(* Logix 5000 project; controller MVI56ADMNETServer 1756-L63 rev 11.1; software revision 11.13 *)
// Example Logic for the MVI56-ADM module.

TASK MainTask (task) : MainProgram

MODULES
   Local : 1756-L63 (rev 11.1)
      ADM : vendor 1 type 0 code 15 (rev 1.1, Output RPI 2 ms)
END_MODULES

TYPE ADMNETModuleDef :
STRUCT
   ReadData : INT[600];
   WriteData : INT[600];
END_STRUCT
END_TYPE

VAR_GLOBAL   (* controller tags *)
   ADMNET : ADMNETModuleDef;
   ColdBoot : BOOL;
   MJFAULTS : DINT[12] := ([0] := -491726278, [1] := 191080, [3] := -495837906, [4] := 191080);
   WarmBoot : BOOL;
END_VAR

PROGRAM MainProgram   (* routine attr 65 MainRoutine *)

ROUTINE MainRoutine   (* ladder *)
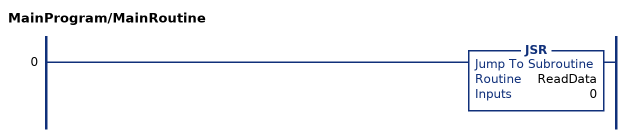
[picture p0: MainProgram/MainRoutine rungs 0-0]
   0: JSR(ReadData,0);
END_ROUTINE

ROUTINE ReadData   (* ladder *)
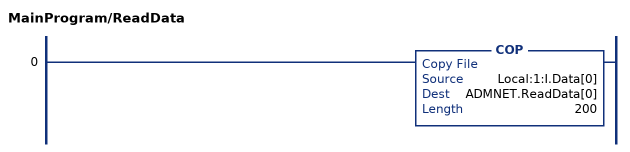
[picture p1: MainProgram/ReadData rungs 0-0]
   0: COP(Local:1:I.Data[0],ADMNET.ReadData[0],200);
END_ROUTINE
END_PROGRAM

PROGRAM StartUp   (* routine attr 65 PowerUp *)

ROUTINE PowerUp   (* ladder *)
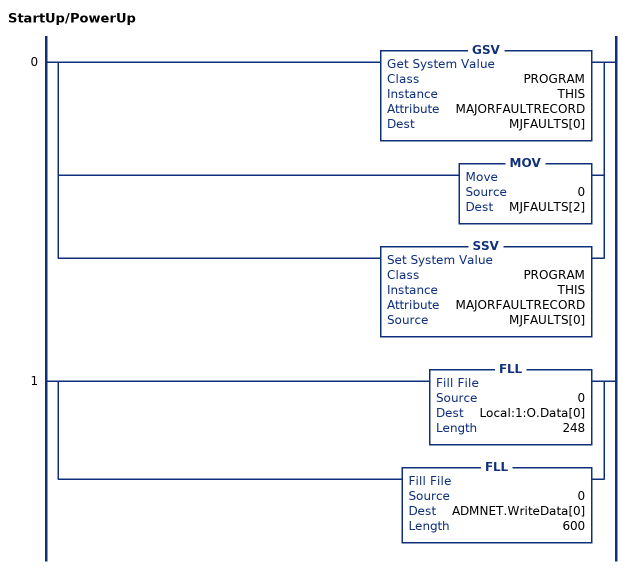
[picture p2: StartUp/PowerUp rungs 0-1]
   0: [GSV(PROGRAM,THIS,MAJORFAULTRECORD,MJFAULTS[0]) ,MOV(0,MJFAULTS[2]) ,SSV(PROGRAM,THIS,MAJORFAULTRECORD,MJFAULTS[0]) ];
   1: [FLL(0,Local:1:O.Data[0],248) ,FLL(0,ADMNET.WriteData[0],600) ];
END_ROUTINE
END_PROGRAM
